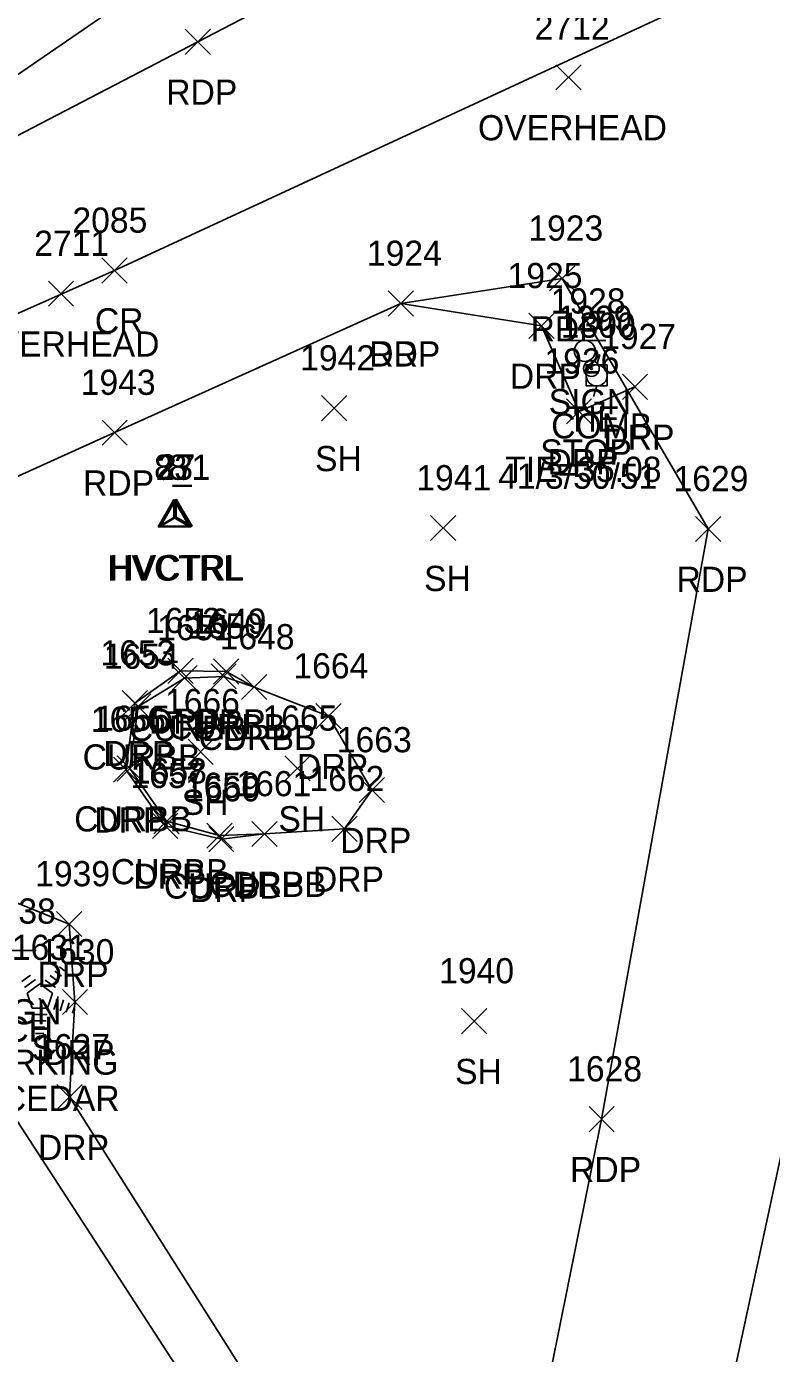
# Model space of a CAD drawing. Extents: x 1477930 to 1480780, y 774090 to 784647.
# Drawn here: x 1479337.8 to 1479397, y 774574.9 to 774680.3 of the extents above; entities that cross this region are included whole.
import ezdxf

# ---------------------------------------------------------------- set-up
doc = ezdxf.new("R2010")
doc.units = 0
for name, color, linetype in [('C_A', 7, 'Continuous'), ('C_C', 7, 'Continuous'), ('C_I', 7, 'Continuous'), ('CBP', 7, 'Continuous'), ('CPSM', 7, 'Continuous'), ('L_A', 7, 'Continuous'), ('L_C', 7, 'Continuous'), ('L_I', 7, 'Continuous'), ('L_TIC', 7, 'Continuous'), ('LBC', 7, 'Continuous'), ('LELB', 7, 'Continuous'), ('LTC', 7, 'Continuous'), ('P_A', 7, 'Continuous'), ('P_I', 7, 'Continuous'), ('P_TIC', 7, 'Continuous'), ('PET', 7, 'Continuous'), ('PRC', 7, 'Continuous'), ('R_A', 7, 'Continuous'), ('R_I', 7, 'Continuous'), ('R_TIC', 7, 'Continuous'), ('RC', 7, 'Continuous'), ('RDP', 7, 'Continuous'), ('S_A', 7, 'Continuous'), ('S_C', 7, 'Continuous'), ('S_I', 7, 'Continuous'), ('SSGN', 7, 'Continuous'), ('U_A', 7, 'Continuous'), ('U_C', 7, 'Continuous'), ('U_I', 7, 'Continuous'), ('U_TIC', 7, 'Continuous'), ('UP', 7, 'Continuous')]:
    doc.layers.add(name, color=color, linetype=linetype)

msp = doc.modelspace()

# ---------------------------------------------------------------- linework, layer by layer
at = {"layer": 'CBP'}
for radius in [0.625, 0.0833]:
    msp.add_circle((1479382.71, 774653.13), radius, dxfattribs=at)
at = {"layer": 'CPSM'}
for p, q in [((1479348.3, 774640.57), (1479349.55, 774642.73)), ((1479348.43, 774640.57), (1479349.68, 774642.73)), ((1479348.43, 774640.57), (1479349.68, 774642.73)), ((1479348.49, 774640.6), (1479349.74, 774642.76)), ((1479350.8, 774640.57), (1479349.55, 774642.73)), ((1479349.55, 774641.29), (1479349.55, 774642.73)), ((1479350.93, 774640.57), (1479349.68, 774642.73)), ((1479349.68, 774641.29), (1479349.68, 774642.73)), ((1479350.93, 774640.57), (1479349.68, 774642.73)), ((1479349.68, 774641.29), (1479349.68, 774642.73)), ((1479350.99, 774640.6), (1479349.74, 774642.76)), ((1479349.74, 774641.32), (1479349.74, 774642.76)), ((1479348.3, 774640.57), (1479349.55, 774641.29)), ((1479348.43, 774640.57), (1479349.68, 774641.29)), ((1479348.43, 774640.57), (1479349.68, 774641.29)), ((1479348.49, 774640.6), (1479349.74, 774641.32)), ((1479349.55, 774641.29), (1479349.55, 774641.29)), ((1479349.55, 774641.29), (1479350.8, 774640.57)), ((1479349.68, 774641.29), (1479349.68, 774641.29)), ((1479349.68, 774641.29), (1479350.93, 774640.57)), ((1479349.68, 774641.29), (1479349.68, 774641.29)), ((1479349.68, 774641.29), (1479350.93, 774640.57)), ((1479349.74, 774641.32), (1479349.74, 774641.32)), ((1479349.74, 774641.32), (1479350.99, 774640.6)), ((1479348.3, 774640.57), (1479350.8, 774640.57)), ((1479348.43, 774640.57), (1479350.93, 774640.57)), ((1479348.43, 774640.57), (1479350.93, 774640.57)), ((1479348.49, 774640.6), (1479350.99, 774640.6))]:
    msp.add_line(p, q, dxfattribs=at)
at = {"layer": 'L_TIC'}
for points in [[(1479361.28, 774648.98), (1479363.28, 774650.98)], [(1479363.28, 774648.98), (1479361.28, 774650.98)], [(1479369.93, 774639.46), (1479371.93, 774641.46)], [(1479371.93, 774639.46), (1479369.93, 774641.46)], [(1479350.68, 774621.68), (1479352.68, 774623.68)], [(1479352.68, 774621.68), (1479350.68, 774623.68)], [(1479358.36, 774620.37), (1479360.36, 774622.37)], [(1479360.36, 774620.37), (1479358.36, 774622.37)], [(1479372.4, 774600.3), (1479374.4, 774602.3)], [(1479374.4, 774600.3), (1479372.4, 774602.3)]]:
    msp.add_lwpolyline(points, dxfattribs=at)
at = {"layer": 'LBC'}
msp.add_lwpolyline([(1479313.99, 774565.07), (1479318.46, 774557.83), (1479321.91, 774559.82), (1479327.98, 774550.43), (1479337.86, 774556.38), (1479345.84, 774561.88), (1479350.43, 774554.62), (1479358.65, 774560.14), (1479331.34, 774602.22)], dxfattribs=at)
at = {"layer": 'LELB'}
msp.add_lwpolyline([(1479244.5, 774634.75), (1479253.67, 774635.16), (1479275, 774646.05), (1479321.56, 774665.78), (1479350.31, 774685.54), (1479389.05, 774723.2), (1479417.5, 774768.3), (1479423.92, 774796.13)], dxfattribs=at)
at = {"layer": 'LTC'}
for p, q in [((1479340.08, 774605.26), (1479340.63, 774604.86)), ((1479340.45, 774605.61), (1479340.87, 774605.3)), ((1479337.47, 774604.44), (1479338.17, 774604.95)), ((1479337.68, 774603.97), (1479338.56, 774604.61)), ((1479337.9, 774603.52), (1479338.91, 774604.25)), ((1479338.91, 774604.25), (1479339.91, 774603.53)), ((1479339.33, 774604.56), (1479340.14, 774603.97)), ((1479339.71, 774604.91), (1479340.38, 774604.42)), ((1479337.9, 774603.52), (1479338.29, 774602.32)), ((1479339.91, 774603.53), (1479339.52, 774602.32)), ((1479340.35, 774603.25), (1479340.01, 774602.22)), ((1479340.79, 774603), (1479340.51, 774602.12)), ((1479339.52, 774602.32), (1479338.29, 774602.32)), ((1479341.24, 774602.75), (1479341, 774602.02)), ((1479341.68, 774602.5), (1479341.5, 774601.93)), ((1479339.48, 774601.82), (1479338.34, 774601.82)), ((1479339.4, 774601.32), (1479338.41, 774601.32)), ((1479339.31, 774600.82), (1479338.48, 774600.82)), ((1479339.23, 774600.32), (1479338.56, 774600.32))]:
    msp.add_line(p, q, dxfattribs=at)
at = {"layer": 'P_TIC'}
for points in [[(1479350.45, 774678.08), (1479352.45, 774680.08)], [(1479352.45, 774678.08), (1479350.45, 774680.08)], [(1479343.83, 774659.92), (1479345.83, 774661.92)], [(1479345.83, 774659.92), (1479343.83, 774661.92)], [(1479379.39, 774659.29), (1479381.39, 774661.29)], [(1479381.39, 774659.29), (1479379.39, 774661.29)], [(1479366.57, 774657.29), (1479368.57, 774659.29)], [(1479368.57, 774657.29), (1479366.57, 774659.29)], [(1479343.84, 774647.04), (1479345.84, 774649.04)], [(1479345.84, 774647.04), (1479343.84, 774649.04)], [(1479390.98, 774639.39), (1479392.98, 774641.39)], [(1479392.98, 774639.39), (1479390.98, 774641.39)], [(1479382.52, 774592.51), (1479384.52, 774594.51)], [(1479384.52, 774592.51), (1479382.52, 774594.51)]]:
    msp.add_lwpolyline(points, dxfattribs=at)
at = {"layer": 'PET'}
for points in [[(1479234.45, 774632.83), (1479239.1, 774628.15), (1479289.14, 774648.12), (1479321.9, 774663.73), (1479351.45, 774679.08), (1479366.99, 774687.18), (1479407.96, 774704.03), (1479416.46, 774738.94), (1479422.81, 774766.95), (1479432.79, 774813.6), (1479435.56, 774829.5), (1479438.63, 774843.63), (1479441.63, 774858.96), (1479447.93, 774875.75)], [(1479290.45, 774211), (1479306.91, 774277.39), (1479311.78, 774295.77), (1479318.73, 774320.25), (1479320.95, 774328.78), (1479324.18, 774341.9), (1479331.38, 774365.72), (1479345.79, 774423.22), (1479362.09, 774490.12), (1479368.03, 774516.32), (1479374.9, 774550.83), (1479383.52, 774593.51), (1479391.98, 774640.39), (1479380.39, 774660.29), (1479367.57, 774658.29), (1479344.84, 774648.04), (1479309.03, 774631.85), (1479275.88, 774616.72), (1479247.66, 774604.4), (1479226.65, 774595.78), (1479182.4, 774576.78), (1479137.48, 774556.65)]]:
    msp.add_lwpolyline(points, dxfattribs=at)
at = {"layer": 'PRC'}
for points in [[(1480015.89, 775005.87), (1479971.79, 774982.46), (1479929.14, 774959.03), (1479892.61, 774942.34), (1479860.44, 774925.31), (1479806.49, 774896.54), (1479658.45, 774815.54), (1479643.75, 774807.57), (1479597.62, 774782.97), (1479555.61, 774761.16), (1479513.42, 774740.32), (1479471, 774718.6), (1479432.73, 774701.1), (1479418.32, 774694.97), (1479344.83, 774660.92), (1479298.6, 774640.39), (1479262.12, 774624.4), (1479219.63, 774609.01), (1479186.74, 774593.83)], [(1479418.32, 774694.97), (1479413.6, 774667.54), (1479403.41, 774616.88), (1479393.18, 774569.31), (1479382.15, 774520.62), (1479370.95, 774473.44), (1479362, 774437.8), (1479350.26, 774392.93), (1479347.88, 774382.5), (1479334.29, 774330.6), (1479333.84, 774328.63), (1479325.02, 774295.54), (1479313.51, 774250.57), (1479296.99, 774187.82), (1479284.93, 774140.68)]]:
    msp.add_lwpolyline(points, dxfattribs=at)
at = {"layer": 'R_TIC'}
for points in [[(1479366.57, 774657.29), (1479368.57, 774659.29)], [(1479368.57, 774657.29), (1479366.57, 774659.29)], [(1479377.74, 774655.52), (1479379.74, 774657.52)], [(1479379.74, 774655.52), (1479377.74, 774657.52)], [(1479385.17, 774650.68), (1479387.17, 774652.68)], [(1479387.17, 774650.68), (1479385.17, 774652.68)], [(1479380.73, 774648.73), (1479382.73, 774650.73)], [(1479382.73, 774648.73), (1479380.73, 774650.73)], [(1479349.07, 774628.12), (1479351.07, 774630.12)], [(1479351.07, 774628.12), (1479349.07, 774630.12)], [(1479349.39, 774627.55), (1479351.39, 774629.55)], [(1479351.39, 774627.55), (1479349.39, 774629.55)], [(1479352.5, 774627.68), (1479354.5, 774629.68)], [(1479354.5, 774627.68), (1479352.5, 774629.68)], [(1479352.7, 774628.07), (1479354.7, 774630.07)], [(1479354.7, 774628.07), (1479352.7, 774630.07)], [(1479354.92, 774626.83), (1479356.92, 774628.83)], [(1479356.92, 774626.83), (1479354.92, 774628.83)], [(1479354.92, 774626.83), (1479356.92, 774628.83)], [(1479356.92, 774626.83), (1479354.92, 774628.83)], [(1479345.45, 774625.55), (1479347.45, 774627.55)], [(1479347.45, 774625.55), (1479345.45, 774627.55)], [(1479345.72, 774625.28), (1479347.72, 774627.28)], [(1479347.72, 774625.28), (1479345.72, 774627.28)], [(1479360.83, 774624.52), (1479362.83, 774626.52)], [(1479362.83, 774624.52), (1479360.83, 774626.52)], [(1479344.74, 774620.27), (1479346.74, 774622.27)], [(1479346.74, 774620.27), (1479344.74, 774622.27)], [(1479345.05, 774620.36), (1479347.05, 774622.36)], [(1479347.05, 774620.36), (1479345.05, 774622.36)], [(1479364.27, 774618.65), (1479366.27, 774620.65)], [(1479366.27, 774618.65), (1479364.27, 774620.65)], [(1479347.85, 774615.81), (1479349.85, 774617.81)], [(1479349.85, 774615.81), (1479347.85, 774617.81)], [(1479347.96, 774616.17), (1479349.96, 774618.17)], [(1479349.96, 774616.17), (1479347.96, 774618.17)], [(1479352.17, 774615.03), (1479354.17, 774617.03)], [(1479354.17, 774615.03), (1479352.17, 774617.03)], [(1479352.32, 774614.75), (1479354.32, 774616.75)], [(1479354.32, 774614.75), (1479352.32, 774616.75)], [(1479355.74, 774615.16), (1479357.74, 774617.16)], [(1479357.74, 774615.16), (1479355.74, 774617.16)], [(1479355.74, 774615.16), (1479357.74, 774617.16)], [(1479357.74, 774615.16), (1479355.74, 774617.16)], [(1479362.1, 774615.57), (1479364.1, 774617.57)], [(1479364.1, 774615.57), (1479362.1, 774617.57)], [(1479340.23, 774608.01), (1479342.23, 774610.01)], [(1479342.23, 774608.01), (1479340.23, 774610.01)], [(1479340.69, 774601.81), (1479342.69, 774603.81)], [(1479342.69, 774601.81), (1479340.69, 774603.81)], [(1479340.26, 774594.27), (1479342.26, 774596.27)], [(1479342.26, 774594.27), (1479340.26, 774596.27)]]:
    msp.add_lwpolyline(points, dxfattribs=at)
at = {"layer": 'RC'}
msp.add_lwpolyline([(1479355.92, 774627.83), (1479353.5, 774628.68), (1479350.39, 774628.55), (1479346.72, 774626.28), (1479346.05, 774621.36), (1479348.96, 774617.17), (1479353.17, 774616.03), (1479356.74, 774616.16)], dxfattribs=at)
at = {"layer": 'RDP'}
for points in [[(1479367.57, 774658.29), (1479378.74, 774656.52), (1479381.73, 774649.73), (1479386.17, 774651.68)], [(1479355.92, 774627.83), (1479353.7, 774629.07), (1479350.07, 774629.12), (1479346.45, 774626.55), (1479345.74, 774621.27), (1479348.85, 774616.81), (1479353.32, 774615.75), (1479356.74, 774616.16), (1479363.1, 774616.57), (1479365.27, 774619.65), (1479361.83, 774625.52)], [(1479361.83, 774625.52), (1479355.92, 774627.83)], [(1479341.23, 774609.01), (1479328.43, 774614.19)], [(1479374.9, 774550.83), (1479371.84, 774556.59), (1479368.53, 774559.58), (1479359.82, 774565.98), (1479341.26, 774595.27), (1479341.69, 774602.81), (1479341.23, 774609.01)]]:
    msp.add_lwpolyline(points, dxfattribs=at)
at = {"layer": 'SSGN'}
for p, q in [((1479380.53, 774655.36), (1479383.86, 774655.36)), ((1479382.18, 774654.53), (1479382.18, 774654.53)), ((1479335.28, 774606.9), (1479338.62, 774606.9))]:
    msp.add_line(p, q, dxfattribs=at)
msp.add_circle((1479382.18, 774654.53), 0.833, dxfattribs=at)
at = {"layer": 'U_TIC'}
for points in [[(1479379.89, 774675.26), (1479381.89, 774677.26)], [(1479381.89, 774675.26), (1479379.89, 774677.26)], [(1479339.58, 774658.08), (1479341.58, 774660.08)], [(1479341.58, 774658.08), (1479339.58, 774660.08)]]:
    msp.add_lwpolyline(points, dxfattribs=at)
at = {"layer": 'UP'}
for p, q in [((1479383.38, 774654.25), (1479383.13, 774653.42)), ((1479382.3, 774651.75), (1479382.3, 774653.42)), ((1479382.3, 774653.42), (1479383.96, 774653.42)), ((1479383.13, 774652.58), (1479383.13, 774652.58)), ((1479383.96, 774653.42), (1479383.96, 774651.75)), ((1479383.96, 774651.75), (1479382.3, 774651.75)), ((1479382.88, 774650.92), (1479383.13, 774651.75))]:
    msp.add_line(p, q, dxfattribs=at)
msp.add_circle((1479383.13, 774652.58), 0.833, dxfattribs=at)

# ---------------------------------------------------------------- texts
at = {"layer": 'C_A'}
for s, p in [('TIE', (1479380.79, 774648.13)), ('HVCTRL', (1479344.25, 774636.29)), ('HVCTRL', (1479344.38, 774636.29)), ('HVCTRL', (1479344.38, 774636.29)), ('HVCTRL', (1479344.44, 774636.32))]:
    msp.add_text(s, height=2, dxfattribs=at).set_placement(p)
at = {"layer": 'C_C'}
msp.add_text('TIE=35.08', height=2, dxfattribs=at).set_placement((1479375.86, 774644.13))
at = {"layer": 'C_I'}
for s, p in [('1299', (1479380.01, 774656.13)), ('8_1', (1479347.97, 774644.29)), ('23', (1479348.09, 774644.29)), ('27', (1479348.28, 774644.32)), ('8', (1479349.12, 774644.29))]:
    msp.add_text(s, height=2, dxfattribs=at).set_placement(p)
at = {"layer": 'L_A'}
for s, p in [('SH', (1479360.76, 774644.98)), ('SH', (1479369.42, 774635.46)), ('SH', (1479350.17, 774617.68)), ('SH', (1479357.85, 774616.37)), ('PORCH', (1479330.29, 774599.66)), ('S', (1479338.24, 774598.16)), ('SH', (1479371.88, 774596.3))]:
    msp.add_text(s, height=2, dxfattribs=at).set_placement(p)
at = {"layer": 'L_C'}
msp.add_text('M.CEDAR', height=2, dxfattribs=at).set_placement((1479332.91, 774594.16))
at = {"layer": 'L_I'}
for s, p in [('1942', (1479359.58, 774652.98)), ('1941', (1479368.8, 774643.46)), ('1666', (1479348.84, 774625.68)), ('1665', (1479356.58, 774624.37)), ('1631', (1479336.68, 774606.16)), ('1940', (1479370.62, 774604.3))]:
    msp.add_text(s, height=2, dxfattribs=at).set_placement(p)
at = {"layer": 'LTC'}
msp.add_text('.', height=1.04, rotation=270, dxfattribs=at).set_placement((1479338.8, 774603.26))
at = {"layer": 'P_A'}
for s, p in [('RDP', (1479348.94, 774674.08)), ('CR', (1479343.27, 774655.92)), ('RDP', (1479377.88, 774655.29)), ('RDP', (1479365.06, 774653.29)), ('RDP', (1479342.33, 774643.04)), ('RDP', (1479389.47, 774635.39)), ('RDP', (1479381.01, 774588.51))]:
    msp.add_text(s, height=2, dxfattribs=at).set_placement(p)
at = {"layer": 'P_I'}
for s, p in [('2085', (1479341.49, 774663.92)), ('1923', (1479377.7, 774663.29)), ('1924', (1479364.88, 774661.29)), ('1943', (1479342.15, 774651.04)), ('1629', (1479389.23, 774643.39)), ('1628', (1479380.78, 774596.51))]:
    msp.add_text(s, height=2, dxfattribs=at).set_placement(p)
at = {"layer": 'R_A'}
for s, p in [('DRP', (1479365.06, 774653.29)), ('DRP', (1479376.23, 774651.52)), ('DRP', (1479383.66, 774646.68)), ('DRP', (1479379.22, 774644.73)), ('CURBB', (1479345.97, 774623.55)), ('DRP', (1479347.56, 774624.12)), ('CURBB', (1479349.09, 774623.68)), ('DRP', (1479351.18, 774624.07)), ('CURBB', (1479351.51, 774622.83)), ('DRP', (1479353.41, 774622.83)), ('CURBB', (1479342.3, 774621.28)), ('DRP', (1479343.94, 774621.55)), ('DRP', (1479359.32, 774620.52)), ('CURBB', (1479341.63, 774616.36)), ('DRP', (1479343.23, 774616.27)), ('DRP', (1479362.76, 774614.65)), ('CURBB', (1479344.54, 774612.17)), ('DRP', (1479346.33, 774611.81)), ('DRP', (1479360.59, 774611.57)), ('CURBB', (1479348.75, 774611.03)), ('DRP', (1479350.81, 774610.75)), ('CURBB', (1479352.32, 774611.16)), ('DRP', (1479354.22, 774611.16)), ('DRP', (1479338.72, 774604.01)), ('DRP', (1479339.18, 774597.81)), ('DRP', (1479338.75, 774590.27))]:
    msp.add_text(s, height=2, dxfattribs=at).set_placement(p)
at = {"layer": 'R_I'}
for s, p in [('1924', (1479364.88, 774661.29)), ('1925', (1479376.05, 774659.52)), ('1927', (1479383.48, 774654.68)), ('1926', (1479378.98, 774652.73)), ('1652', (1479347.33, 774632.12)), ('1651', (1479348.22, 774631.55)), ('1650', (1479350.68, 774631.68)), ('1649', (1479350.95, 774632.07)), ('1648', (1479353.18, 774630.83)), ('1648', (1479353.18, 774630.83)), ('1653', (1479343.71, 774629.55)), ('1654', (1479343.98, 774629.28)), ('1664', (1479359.04, 774628.52)), ('1656', (1479342.95, 774624.27)), ('1655', (1479343.31, 774624.36)), ('1663', (1479362.49, 774622.65)), ('1658', (1479346.22, 774620.17)), ('1657', (1479346.1, 774619.81)), ('1659', (1479350.42, 774619.03)), ('1661', (1479354.51, 774619.16)), ('1661', (1479354.51, 774619.16)), ('1662', (1479360.31, 774619.57)), ('1660', (1479350.45, 774618.75)), ('1939', (1479338.53, 774612.01)), ('1630', (1479338.87, 774605.81)), ('1627', (1479338.52, 774598.27))]:
    msp.add_text(s, height=2, dxfattribs=at).set_placement(p)
at = {"layer": 'S_A'}
for p in [(1479379.32, 774649.5), (1479334.07, 774601.04)]:
    msp.add_text('SIGN', height=2, dxfattribs=at).set_placement(p)
at = {"layer": 'S_C'}
for s, p in [('STOP', (1479378.64, 774645.5)), ('NO PARKING', (1479328.35, 774597.04))]:
    msp.add_text(s, height=2, dxfattribs=at).set_placement(p)
at = {"layer": 'S_I'}
for s, p in [('1928', (1479379.47, 774657.5)), ('1938', (1479334.22, 774609.04))]:
    msp.add_text(s, height=2, dxfattribs=at).set_placement(p)
at = {"layer": 'U_A'}
for s, p in [('OVERHEAD', (1479373.7, 774671.26)), ('OVERHEAD', (1479333.39, 774654.08)), ('COMB', (1479379.52, 774647.58))]:
    msp.add_text(s, height=2, dxfattribs=at).set_placement(p)
at = {"layer": 'U_C'}
msp.add_text('41/3/50/51', height=2, dxfattribs=at).set_placement((1479375.3, 774643.58))
at = {"layer": 'U_I'}
for s, p in [('2712', (1479378.2, 774679.26)), ('2711', (1479338.45, 774662.08)), ('1300', (1479380.27, 774655.58))]:
    msp.add_text(s, height=2, dxfattribs=at).set_placement(p)

doc.saveas('drawing.dxf')
